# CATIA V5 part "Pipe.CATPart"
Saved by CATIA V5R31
Part number: Pipe
Bounding box of the stored display mesh (mm): x -50 to 50, y 0 to 150, z -50 to 50
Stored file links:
  D:\PROJECTS\Project 2021\US EDITION\CATIA V5 6R 2021\Resources\Part Files\c12_catia_v5_6r2021_prt\c12_catia_v5-6r2021 figr_12-39\Pipe.CATPart
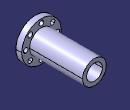
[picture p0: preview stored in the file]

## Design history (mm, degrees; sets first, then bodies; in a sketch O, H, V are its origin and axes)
Body1 (main body)
  Sketch1 on zx-plane, origin (0, 0, 0), H (-1, 0, 0), V (0, 0, 1)
    circle A1 centre (0, 0) radius 50
    point P1 (0, -50)
    circle A2 centre (0, 0) radius 30
    point P2 (0, -30)
    radius A1 = 50
    radius A2 = 30
    coincidence: A1 P1, P1 V, A2 P2, P2 V
  MultiPad1: profile Sketch1, domains (length 150; length 15)
  Sketch2 on face of MultiPad1, origin (0, 150, 0), H (-1, 0, 0), V (0, 0, 1)
    circle A1 centre (0, 0) radius 20
    point P1 (0, -20)
    radius A1 = 20
    coincidence: A1 P1, P1 V
  Pocket1: profile Sketch2, direction (0, -1, 0), through (limit type 3)
  Sketch3 on face of MultiPad1, origin (0, 0, 0), H (1, 0, 0), V (0, 0, 1)
    circle A1 centre (0, -40) radius 6
    point P1 (0, -40)
    radius A1 = 6
    distance H P1 = 40
    coincidence: P1 V
  Pocket2: profile Sketch3, direction (0, 1, 0), through (limit type 3)
  CircPattern1: of Pocket2, instances 8, angular step 45, axis from face of MultiPad1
